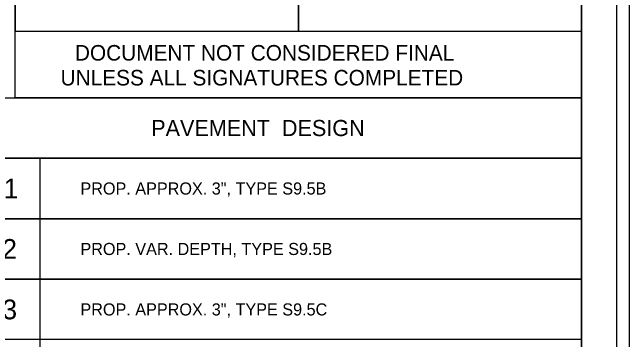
# Model space of a CAD drawing. Extents: x 2320980 to 2456309, y 595047 to 606177.
# Drawn here: x 2456001.89 to 2456045.51, y 596904.26 to 596927.41 of the extents above; entities that cross this region are included whole.
import ezdxf

# ---------------------------------------------------------------- set-up
doc = ezdxf.new("R2010")
doc.units = 0
for name, color, linetype in [('Prop Dimension', 7, 'Continuous'), ('Prop Pavement Schedule Description CELL', 7, 'Continuous'), ('Sheet Plan CELL', 7, 'Continuous'), ('Sheet Plot Border Inside CELL', 7, 'Continuous'), ('Sheet Plot Border Outside CELL', 7, 'Continuous'), ('Sheet Sticker Exception Certification CELL', 7, 'Continuous')]:
    doc.layers.add(name, color=color, linetype=linetype)

msp = doc.modelspace()

# ---------------------------------------------------------------- linework, layer by layer
at = {"layer": 'Prop Dimension'}
msp.add_line((2456003.83, 596917.09), (2456003.83, 596823.591), dxfattribs=at)
for points in [[(2455998.637, 596921.366), (2456042.107, 596921.366), (2456042.107, 596917.09), (2455998.637, 596917.09)], [(2455998.637, 596917.09), (2456042.106, 596917.09), (2456042.106, 596912.814), (2455998.637, 596912.814)], [(2455998.637, 596912.814), (2456042.106, 596912.814), (2456042.106, 596908.538), (2455998.637, 596908.538)], [(2455998.637, 596908.538), (2456042.106, 596908.538), (2456042.106, 596904.262), (2455998.637, 596904.262)]]:
    msp.add_lwpolyline(points, close=True, dxfattribs=at)
at = {"layer": 'Sheet Plan CELL'}
for points in [[(2455742.104, 596746.076), (2455742.099, 596956.071), (2456002.097, 596956.079), (2456002.099, 596926.066), (2456042.107, 596926.064), (2456042.107, 596746.076)], [(2456042.112, 596956.076), (2455742.104, 596956.076), (2455742.104, 596746.076), (2456042.107, 596746.076)], [(2456002.097, 596948.564), (2456022.107, 596948.564), (2456022.107, 596926.061), (2456002.099, 596926.066)], [(2456022.107, 596948.564), (2456042.104, 596948.566), (2456042.107, 596926.064), (2456022.107, 596926.061)]]:
    msp.add_lwpolyline(points, close=True, dxfattribs=at)
at = {"layer": 'Sheet Plot Border Inside CELL'}
msp.add_lwpolyline([(2455711.407, 596745.574), (2456044.604, 596745.576), (2456044.607, 596956.574), (2455711.407, 596956.574)], close=True, dxfattribs=at)
at = {"layer": 'Sheet Plot Border Outside CELL'}
msp.add_lwpolyline([(2455708.807, 596741.574), (2456045.507, 596741.574), (2456045.507, 596960.574), (2455708.807, 596960.574)], close=True, dxfattribs=at)
at = {"layer": 'Sheet Sticker Exception Certification CELL'}
for p, q in [((2456002.099, 596921.366), (2456002.099, 596926.066)), ((2456002.099, 596926.066), (2456042.107, 596926.066)), ((2456042.107, 596926.064), (2456042.107, 596921.364)), ((2456042.107, 596921.366), (2456002.099, 596921.366))]:
    msp.add_line(p, q, dxfattribs=at)

# ---------------------------------------------------------------- texts
at = {"layer": 'Prop Pavement Schedule Description CELL'}
for s, height, p in [('PAVEMENT  DESIGN', 1.14031, (2456011.704, 596918.658)), ('C1', 1.3969, (2455999.929, 596914.254)), ('PROP. APPROX. 3", TYPE S9.5B', 0.85523, (2456006.703, 596914.525)), ('C2', 1.3969, (2455999.831, 596909.978)), ('PROP. VAR. DEPTH, TYPE S9.5B', 0.85523, (2456006.703, 596910.248)), ('C3', 1.3969, (2455999.839, 596905.701)), ('PROP. APPROX. 3", TYPE S9.5C', 0.85523, (2456006.703, 596905.972))]:
    msp.add_text(s, height=height, dxfattribs=at).set_placement(p)
at = {"layer": 'Sheet Sticker Exception Certification CELL'}
for s, p in [('DOCUMENT NOT CONSIDERED FINAL', (2456006.313, 596923.997)), ('UNLESS ALL SIGNATURES COMPLETED', (2456005.299, 596922.237))]:
    msp.add_text(s, height=1.1, dxfattribs=at).set_placement(p)

doc.saveas('drawing.dxf')
